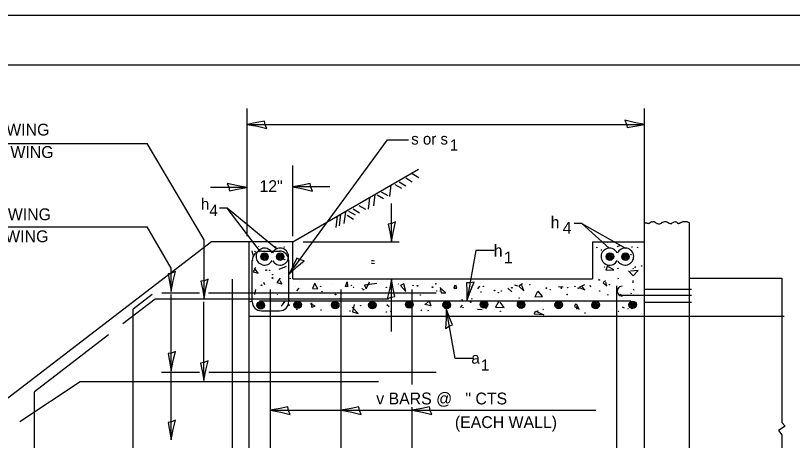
# Model space of a CAD drawing. Extents: x 2133490 to 2172050, y 2138301 to 2145980.
# Drawn here: x 2143369.1 to 2143762.6, y 2145459.3 to 2145674.5 of the extents above; entities that cross this region are included whole.
import ezdxf

# ---------------------------------------------------------------- set-up
doc = ezdxf.new("R2010")
doc.units = 0
for name, color, linetype in [('Level 40', 7, 'Continuous'), ('Level 63', 7, 'Continuous'), ('ROW_PR_Notes', 7, 'Continuous'), ('Sheets_50 Reference Boundary', 7, 'Continuous'), ('Sheets_General Details', 7, 'Continuous'), ('Sheets_Printer Plotting Border', 7, 'Continuous')]:
    doc.layers.add(name, color=color, linetype=linetype)

msp = doc.modelspace()

# ---------------------------------------------------------------- linework, layer by layer
at = {"layer": 'Level 40'}
for p, q in [((2143656, 2145569.17), (2143651.99, 2145569.17)), ((2143669.72, 2145556.75), (2143656, 2145569.17)), ((2143656, 2145569.17), (2143677.98, 2145556.74)), ((2143687.75, 2145535.94), (2143711.4, 2145535.94)), ((2143711.4, 2145532.64), (2143687.75, 2145532.64)), ((2143687.75, 2145529.34), (2143711.4, 2145529.34)), ((2143687.74, 2145522.23), (2143734.89, 2145522.23)), ((2143734.89, 2145522.23), (2143758.47, 2145522.23))]:
    msp.add_line(p, q, dxfattribs=at)
for centre, radius in [((2143505.18, 2145557.27), 0.0943), ((2143663.47, 2145557.02), 0.0943), ((2143668.62, 2145559.72), 0.0943), ((2143681.38, 2145557.27), 0.0943), ((2143684.08, 2145557.02), 0.0943), ((2143490.46, 2145555.06), 0.0943), ((2143495.22, 2145552.4), 1.89), ((2143494.2, 2145552.74), 0.472), ((2143495.22, 2145552.4), 1.41), ((2143495.22, 2145552.4), 0.943), ((2143494.88, 2145552.74), 0.472), ((2143495.22, 2145552.4), 0.472), ((2143496.24, 2145552.06), 0.472), ((2143503.13, 2145552.4), 1.89), ((2143502.11, 2145552.74), 0.472), ((2143503.13, 2145552.4), 1.41), ((2143503.13, 2145552.4), 0.943), ((2143502.79, 2145552.74), 0.472), ((2143503.13, 2145552.4), 0.472), ((2143504.16, 2145552.06), 0.472), ((2143670.17, 2145552.4), 1.89), ((2143669.14, 2145552.74), 0.472), ((2143670.17, 2145552.4), 1.41), ((2143670.17, 2145552.4), 0.943), ((2143669.82, 2145552.74), 0.472), ((2143670.17, 2145552.4), 0.472), ((2143671.19, 2145552.06), 0.472), ((2143678.08, 2145552.4), 1.89), ((2143677.06, 2145552.74), 0.472), ((2143676.72, 2145552.61), 0.0943), ((2143678.08, 2145552.4), 1.41), ((2143678.08, 2145552.4), 0.943), ((2143677.74, 2145552.74), 0.472), ((2143678.08, 2145552.4), 0.472), ((2143679.1, 2145552.06), 0.472), ((2143680.89, 2145553.34), 0.0943), ((2143488.99, 2145550.4), 0.0943), ((2143496.35, 2145550.64), 0.0943), ((2143505.43, 2145550.89), 0.0943), ((2143496.1, 2145545.49), 0.189), ((2143497.82, 2145545.49), 0.0943), ((2143667.39, 2145547.21), 0.0943), ((2143674.26, 2145546.47), 0.0943), ((2143681.87, 2145546.22), 0.0943), ((2143686.29, 2145547.7), 0.0943), ((2143499.29, 2145541.56), 0.189), ((2143499.29, 2145543.28), 0.0943), ((2143508.13, 2145541.32), 0.0943), ((2143664.69, 2145540.58), 0.189), ((2143674.26, 2145541.32), 0.0943), ((2143493.65, 2145537.88), 0.189), ((2143523.59, 2145537.39), 0.0943), ((2143539.29, 2145537.88), 0.0943), ((2143540.28, 2145536.9), 0.0943), ((2143556.96, 2145536.9), 0.0943), ((2143570.46, 2145537.88), 0.0943), ((2143572.67, 2145537.64), 0.189), ((2143580.28, 2145536.9), 0.189), ((2143581.99, 2145538.62), 0.0943), ((2143600.15, 2145536.9), 0.189), ((2143606.04, 2145537.39), 0.0943), ((2143620.52, 2145536.65), 0.189), ((2143629.6, 2145538.13), 0.0943), ((2143648.74, 2145536.65), 0.0943), ((2143652.42, 2145537.39), 0.0943), ((2143669.85, 2145538.13), 0.0943), ((2143524.32, 2145534.69), 0.0943), ((2143531.2, 2145533.22), 0.189), ((2143544.69, 2145536.16), 0.0943), ((2143545.43, 2145535.67), 0.189), ((2143574.14, 2145532.97), 0.0943), ((2143582.48, 2145534.94), 0.0943), ((2143604.82, 2145534.45), 0.0943), ((2143611.69, 2145535.18), 0.189), ((2143613.65, 2145534.2), 0.0943), ((2143615.12, 2145534.94), 0.0943), ((2143637.94, 2145536.41), 0.189), ((2143639.91, 2145535.67), 0.0943), ((2143645.55, 2145536.41), 0.189), ((2143648.5, 2145533.22), 0.0943), ((2143654.14, 2145536.41), 0.189), ((2143664.94, 2145534.94), 0.0943), ((2143675.49, 2145533.22), 0.0943), ((2143680.89, 2145533.71), 0.0943), ((2143488.25, 2145529.54), 0.0943), ((2143493.29, 2145527.76), 1.89), ((2143493.29, 2145527.76), 1.41), ((2143507.88, 2145530.03), 0.0943), ((2143512, 2145528.01), 1.89), ((2143512, 2145528.01), 1.41), ((2143512, 2145528.01), 0.943), ((2143531.04, 2145527.84), 1.89), ((2143531.04, 2145527.84), 1.41), ((2143549.83, 2145527.84), 1.89), ((2143549.83, 2145527.84), 1.41), ((2143548.62, 2145529.78), 0.0943), ((2143568.54, 2145528.17), 1.89), ((2143567.52, 2145528.51), 0.472), ((2143568.54, 2145528.17), 1.41), ((2143568.54, 2145528.17), 0.943), ((2143568.2, 2145528.51), 0.472), ((2143587.5, 2145527.92), 1.89), ((2143587.5, 2145527.92), 1.41), ((2143595.25, 2145530.52), 0.0943), ((2143599.66, 2145529.29), 0.189), ((2143600.15, 2145531.01), 0.0943), ((2143606.37, 2145528.17), 1.89), ((2143605.35, 2145528.51), 0.472), ((2143606.37, 2145528.17), 1.41), ((2143606.37, 2145528.17), 0.943), ((2143606.03, 2145528.51), 0.472), ((2143625.16, 2145528.09), 1.89), ((2143624.14, 2145528.43), 0.472), ((2143625.16, 2145528.09), 1.41), ((2143624.2, 2145531.5), 0.0943), ((2143625.16, 2145528.09), 0.943), ((2143624.82, 2145528.43), 0.472), ((2143644.2, 2145527.92), 1.89), ((2143644.2, 2145527.92), 1.41), ((2143662.91, 2145527.92), 1.89), ((2143662.91, 2145527.92), 1.41), ((2143681.7, 2145528.01), 1.89), ((2143681.7, 2145528.01), 1.41), ((2143681.7, 2145528.01), 0.943), ((2143492.26, 2145528.1), 0.472), ((2143493.29, 2145527.76), 0.943), ((2143492.95, 2145528.1), 0.472), ((2143493.29, 2145527.76), 0.472), ((2143494.31, 2145527.42), 0.472), ((2143495.12, 2145524.88), 0.0943), ((2143507.64, 2145527.82), 0.189), ((2143510.97, 2145528.35), 0.472), ((2143511.66, 2145528.35), 0.472), ((2143511.56, 2145525.61), 0.0943), ((2143512, 2145528.01), 0.472), ((2143513.02, 2145527.67), 0.472), ((2143523.83, 2145525.37), 0.0943), ((2143530.01, 2145528.18), 0.472), ((2143531.04, 2145527.84), 0.943), ((2143530.7, 2145528.18), 0.472), ((2143531.04, 2145527.84), 0.472), ((2143532.06, 2145527.5), 0.472), ((2143538.56, 2145524.88), 0.0943), ((2143543.96, 2145527.58), 0.0943), ((2143548.81, 2145528.18), 0.472), ((2143549.83, 2145527.84), 0.943), ((2143549.49, 2145528.18), 0.472), ((2143549.83, 2145527.84), 0.472), ((2143550.85, 2145527.5), 0.472), ((2143568.54, 2145528.17), 0.472), ((2143569.56, 2145527.83), 0.472), ((2143578.07, 2145525.12), 0.0943), ((2143586.47, 2145528.26), 0.472), ((2143587.5, 2145527.92), 0.943), ((2143587.15, 2145528.26), 0.472), ((2143587.5, 2145527.92), 0.472), ((2143587.88, 2145528.31), 0.189), ((2143588.52, 2145527.58), 0.472), ((2143595.74, 2145526.59), 0.0943), ((2143606.37, 2145528.17), 0.472), ((2143607.39, 2145527.83), 0.472), ((2143607.27, 2145526.35), 0.189), ((2143625.16, 2145528.09), 0.472), ((2143626.18, 2145527.75), 0.472), ((2143633.53, 2145524.88), 0.0943), ((2143643.18, 2145528.26), 0.472), ((2143644.2, 2145527.92), 0.943), ((2143643.86, 2145528.26), 0.472), ((2143644.2, 2145527.92), 0.472), ((2143645.22, 2145527.58), 0.472), ((2143661.89, 2145528.26), 0.472), ((2143662.91, 2145527.92), 0.943), ((2143662.57, 2145528.26), 0.472), ((2143662.91, 2145527.92), 0.472), ((2143663.93, 2145527.58), 0.472), ((2143680.68, 2145528.35), 0.472), ((2143681.36, 2145528.35), 0.472), ((2143681.7, 2145528.01), 0.472), ((2143681.38, 2145526.1), 0.0943), ((2143682.73, 2145527.67), 0.472), ((2143556.96, 2145524.39), 0.0943), ((2143614.63, 2145524.63), 0.0943), ((2143657.58, 2145523.89), 0.0943), ((2143674.51, 2145524.63), 0.0943)]:
    msp.add_circle(centre, radius, dxfattribs=at)
for centre, start, end in [((2143495.22, 2145552.4), 24.9941, 332.0982), ((2143503.13, 2145552.4), 209.5562, 156.8179), ((2143669.99, 2145552.39), 24.9941, 332.0982), ((2143677.91, 2145552.39), 209.5562, 156.8179)]:
    msp.add_arc(centre, 4.3, start, end, dxfattribs=at)
msp.add_spline([(2143687.73, 2145569.53), (2143688.74, 2145569.46), (2143689.34, 2145569.25), (2143690.07, 2145569.25), (2143690.42, 2145569.42), (2143691.02, 2145569.93), (2143691.36, 2145570.11), (2143691.79, 2145570.02), (2143692.61, 2145570.19), (2143693.43, 2145569.46), (2143693.98, 2145569.16), (2143694.71, 2145569.03), (2143695.23, 2145568.99), (2143695.7, 2145569.16), (2143696.39, 2145569.55), (2143696.69, 2145569.76), (2143696.95, 2145569.81), (2143697.89, 2145570.24), (2143698.54, 2145570.15), (2143699.05, 2145569.98), (2143699.74, 2145569.59), (2143700.64, 2145569.12), (2143700.9, 2145569.08), (2143701.33, 2145569.12), (2143701.76, 2145569.42), (2143702.49, 2145569.89), (2143703.01, 2145570.11), (2143703.65, 2145569.98), (2143704.3, 2145569.55), (2143704.43, 2145569.38), (2143704.68, 2145569.2), (2143705.24, 2145569.29), (2143705.76, 2145569.51), (2143706.74, 2145570.02), (2143707.52, 2145570.24), (2143708.29, 2145570.19), (2143709.06, 2145570.11), (2143709.75, 2145569.81), (2143710.4, 2145569.42)], degree=3, dxfattribs=at)
at = {"layer": 'Level 63'}
for p, q in [((2143507.65, 2145543.5), (2143557.52, 2145611.46)), ((2143557.52, 2145611.46), (2143568.06, 2145611.46)), ((2143509.5, 2145562.78), (2143509.5, 2145598.58)), ((2143486.31, 2145587.4), (2143467.89, 2145587.4)), ((2143528.25, 2145587.7), (2143509.5, 2145587.7))]:
    msp.add_line(p, q, dxfattribs=at)
for points in [[(2143496.35, 2145617.27), (2143495.54, 2145619.19), (2143495.22, 2145621.03), (2143491.35, 2145620.23), (2143486.35, 2145619.36), (2143491.69, 2145618.39)], [(2143677.75, 2145621.45), (2143678.56, 2145619.53), (2143678.87, 2145617.69), (2143682.74, 2145618.49), (2143687.74, 2145619.36), (2143682.41, 2145620.33)], [(2143476.31, 2145589.49), (2143477.12, 2145587.57), (2143477.44, 2145585.73), (2143481.31, 2145586.53), (2143486.31, 2145587.4), (2143480.97, 2145588.37)], [(2143519.5, 2145585.61), (2143518.68, 2145587.53), (2143518.37, 2145589.37), (2143514.5, 2145588.56), (2143509.5, 2145587.7), (2143514.83, 2145586.73)], [(2143561.61, 2145569.95), (2143559.69, 2145569.14), (2143557.84, 2145568.82), (2143558.65, 2145564.95), (2143559.52, 2145559.95), (2143560.49, 2145565.29)], [(2143515.25, 2145550.32), (2143513.22, 2145550.8), (2143511.55, 2145551.64), (2143509.91, 2145548.04), (2143507.65, 2145543.5), (2143511.59, 2145547.23)], [(2143450.11, 2145544.79), (2143448.18, 2145543.97), (2143446.34, 2145543.66), (2143447.15, 2145539.79), (2143448.01, 2145534.79), (2143448.98, 2145540.12)], [(2143466.7, 2145541.02), (2143464.77, 2145540.21), (2143462.93, 2145539.89), (2143463.74, 2145536.02), (2143464.6, 2145531.02), (2143465.57, 2145536.36)], [(2143557.42, 2145531.05), (2143559.35, 2145531.87), (2143561.19, 2145532.18), (2143560.38, 2145536.05), (2143559.52, 2145541.05), (2143558.55, 2145535.72)], [(2143601.45, 2145539.53), (2143599.42, 2145539.07), (2143597.55, 2145539.09), (2143597.66, 2145535.13), (2143597.63, 2145530.06), (2143599.53, 2145535.14)], [(2143586.96, 2145516.03), (2143588.71, 2145517.17), (2143590.47, 2145517.8), (2143588.99, 2145521.47), (2143587.26, 2145526.24), (2143587.24, 2145520.82)], [(2143450.11, 2145504.4), (2143448.18, 2145503.58), (2143446.34, 2145503.27), (2143447.15, 2145499.4), (2143448.01, 2145494.4), (2143448.98, 2145499.73)], [(2143466.62, 2145499.59), (2143464.7, 2145498.78), (2143462.86, 2145498.46), (2143463.66, 2145494.59), (2143464.53, 2145489.59), (2143465.5, 2145494.93)], [(2143508.13, 2145472.49), (2143507.31, 2145474.41), (2143507, 2145476.25), (2143503.13, 2145475.45), (2143498.13, 2145474.58), (2143503.46, 2145473.61)], [(2143544.09, 2145472.49), (2143543.28, 2145474.41), (2143542.96, 2145476.25), (2143539.09, 2145475.45), (2143534.09, 2145474.58), (2143539.43, 2145473.61)], [(2143579.93, 2145472.49), (2143579.12, 2145474.41), (2143578.8, 2145476.25), (2143574.93, 2145475.45), (2143569.93, 2145474.58), (2143575.27, 2145473.61)], [(2143450.11, 2145469.56), (2143448.18, 2145468.75), (2143446.34, 2145468.43), (2143447.15, 2145464.56), (2143448.01, 2145459.56), (2143448.98, 2145464.9)]]:
    msp.add_lwpolyline(points, close=True, dxfattribs=at)
at = {"layer": 'ROW_PR_Notes'}
for p, q in [((2143486.35, 2145562.78), (2143486.35, 2145627.41)), ((2143687.74, 2145562.78), (2143687.74, 2145627.41)), ((2143486.35, 2145619.36), (2143687.74, 2145619.36)), ((2143266.28, 2145609.67), (2143435.74, 2145609.67)), ((2143464.6, 2145560.86), (2143435.74, 2145609.67)), ((2143509.5, 2145559.95), (2143573.13, 2145596.69)), ((2143566.78, 2145592.3), (2143570.08, 2145590.34)), ((2143570.08, 2145594.4), (2143573.39, 2145592.45)), ((2143559.27, 2145588.69), (2143558.52, 2145582.84)), ((2143561.22, 2145588.99), (2143564.53, 2145587.04)), ((2143563.48, 2145590.19), (2143566.78, 2145588.24)), ((2143554.32, 2145585.24), (2143557.62, 2145583.29)), ((2143548.46, 2145582.24), (2143547.71, 2145576.38)), ((2143551.16, 2145583.89), (2143550.41, 2145578.03)), ((2143552.22, 2145583.74), (2143555.52, 2145581.79)), ((2143476.38, 2145576.98), (2143472.37, 2145576.98)), ((2143501.28, 2145556.3), (2143476.38, 2145576.98)), ((2143493.17, 2145554.8), (2143476.38, 2145576.98)), ((2143540.05, 2145576.53), (2143543.36, 2145574.58)), ((2143543.06, 2145578.33), (2143546.36, 2145576.38)), ((2143559.52, 2145559.95), (2143559.52, 2145579.26)), ((2143532.09, 2145572.93), (2143531.34, 2145567.07)), ((2143533.75, 2145573.83), (2143532.99, 2145567.97)), ((2143536.15, 2145575.03), (2143535.4, 2145569.17)), ((2143537.05, 2145573.38), (2143540.35, 2145571.42)), ((2143537.8, 2145575.48), (2143541.1, 2145573.53)), ((2143687.74, 2145559.99), (2143687.74, 2145569.42)), ((2143710.4, 2145308.17), (2143710.4, 2145569.42)), ((2143266.5, 2145567.48), (2143435.84, 2145567.48)), ((2143448.01, 2145546.5), (2143435.84, 2145567.48)), ((2143464.6, 2145531.02), (2143464.6, 2145560.86)), ((2143468.41, 2145559.95), (2143355.43, 2145473.2)), ((2143509.5, 2145559.95), (2143468.41, 2145559.95)), ((2143509.5, 2145559.95), (2143486.35, 2145559.95)), ((2143487.45, 2145308.17), (2143487.45, 2145559.95)), ((2143492.18, 2145557.51), (2143492.18, 2145557.27)), ((2143501.26, 2145557.02), (2143500.03, 2145557.51)), ((2143509.5, 2145541.09), (2143509.5, 2145559.95)), ((2143514.8, 2145559.95), (2143563.44, 2145559.95)), ((2143661.3, 2145559.95), (2143687.74, 2145559.95)), ((2143661.3, 2145559.95), (2143661.3, 2145541.09)), ((2143673.77, 2145557.51), (2143675.25, 2145558)), ((2143687.74, 2145371.35), (2143687.74, 2145559.99)), ((2143488.73, 2145555.29), (2143489.28, 2145553.13)), ((2143493.7, 2145555.19), (2143502.82, 2145555.19)), ((2143665.67, 2145556.04), (2143665.67, 2145555.55)), ((2143488.98, 2145529.69), (2143488.98, 2145550.47)), ((2143507.54, 2145529.69), (2143507.54, 2145550.47)), ((2143448.01, 2145534.79), (2143448.01, 2145546.5)), ((2143490.7, 2145546.96), (2143489.48, 2145544.75)), ((2143489.48, 2145544.75), (2143491.93, 2145544.02)), ((2143491.93, 2145544.02), (2143490.21, 2145546.47)), ((2143502.61, 2145546.1), (2143506.39, 2145547.54)), ((2143668.87, 2145547.7), (2143668.13, 2145545.49)), ((2143668.13, 2145545.49), (2143672.06, 2145545.73)), ((2143672.06, 2145545.73), (2143669.36, 2145547.21)), ((2143679.55, 2145545.2), (2143681.89, 2145542.68)), ((2143684.41, 2145545.38), (2143680.63, 2145545.02)), ((2143681.89, 2145542.68), (2143684.41, 2145545.38)), ((2143683.1, 2145547.45), (2143682.61, 2145546.72)), ((2143479.06, 2145313.71), (2143479.06, 2145541.01)), ((2143497.57, 2145544.26), (2143497.57, 2145544.26)), ((2143503.22, 2145541.56), (2143501.5, 2145539.35)), ((2143509.5, 2145541.09), (2143661.3, 2145541.09)), ((2143559.52, 2145514.48), (2143559.52, 2145541.05)), ((2143710.14, 2145541.4), (2143757.29, 2145541.4)), ((2143757.29, 2145541.4), (2143757.29, 2145468.37)), ((2143495.4, 2145538.17), (2143494.86, 2145539.25)), ((2143501.5, 2145539.35), (2143503.96, 2145538.62)), ((2143503.96, 2145538.62), (2143503.22, 2145540.09)), ((2143510.9, 2145537.09), (2143510.9, 2145537.09)), ((2143513.04, 2145539.6), (2143513.04, 2145539.6)), ((2143520.63, 2145538.9), (2143519.55, 2145536.19)), ((2143522.25, 2145536.01), (2143520.63, 2145538.72)), ((2143520.64, 2145538.37), (2143521.14, 2145538.62)), ((2143529.72, 2145538.62), (2143529.72, 2145538.62)), ((2143536.3, 2145537.27), (2143537.02, 2145539.62)), ((2143537.56, 2145537.27), (2143536.3, 2145537.27)), ((2143537.02, 2145539.62), (2143537.2, 2145537.27)), ((2143537.09, 2145537.14), (2143537.09, 2145537.14)), ((2143552.06, 2145538.86), (2143545.92, 2145537.88)), ((2143545.92, 2145537.88), (2143546.66, 2145536.16)), ((2143546.66, 2145536.16), (2143548.37, 2145539.6)), ((2143562.85, 2145538.62), (2143563.1, 2145538.37)), ((2143565.85, 2145538.53), (2143564.05, 2145537.81)), ((2143564.05, 2145537.81), (2143566.75, 2145534.75)), ((2143566.75, 2145534.75), (2143565.85, 2145538.53)), ((2143591.56, 2145537.88), (2143591.07, 2145536.41)), ((2143592.54, 2145536.41), (2143592.05, 2145537.88)), ((2143604.08, 2145537.39), (2143603.1, 2145536.16)), ((2143623.46, 2145537.39), (2143621.99, 2145537.88)), ((2143625.85, 2145538.53), (2143624.05, 2145537.45)), ((2143624.05, 2145537.45), (2143626.57, 2145535.11)), ((2143626.57, 2145535.11), (2143625.49, 2145537.81)), ((2143646.53, 2145536.9), (2143644.08, 2145537.14)), ((2143657.2, 2145538.17), (2143654.5, 2145536.73)), ((2143657.38, 2145535.65), (2143656.12, 2145537.09)), ((2143660.03, 2145537.88), (2143660.28, 2145537.14)), ((2143667.88, 2145540.09), (2143666.66, 2145539.11)), ((2143666.66, 2145539.11), (2143668.62, 2145537.39)), ((2143668.62, 2145537.39), (2143668.13, 2145539.35)), ((2143673.61, 2145393.47), (2143673.61, 2145537.55)), ((2143681.87, 2145539.11), (2143681.87, 2145540.33)), ((2143438.25, 2145533.21), (2143428.67, 2145525.86)), ((2143443.21, 2145534.02), (2143462.28, 2145534.02)), ((2143448.01, 2145494.4), (2143448.01, 2145533.29)), ((2143466.78, 2145534.02), (2143582.12, 2145534.02)), ((2143490.7, 2145535.67), (2143490.21, 2145533.22)), ((2143498.27, 2145393.16), (2143498.27, 2145535.74)), ((2143501.75, 2145533.22), (2143501.75, 2145533.46)), ((2143511.62, 2145535.11), (2143512.7, 2145536.37)), ((2143515.74, 2145535.18), (2143515.74, 2145535.18)), ((2143519.55, 2145536.19), (2143522.25, 2145536.01)), ((2143534.1, 2145393.16), (2143534.1, 2145535.74)), ((2143569.93, 2145487.64), (2143569.93, 2145535.74)), ((2143583.96, 2145535.18), (2143584.2, 2145534.94)), ((2143584.23, 2145536.73), (2143584.77, 2145534.03)), ((2143587.11, 2145534.03), (2143584.23, 2145536.55)), ((2143584.77, 2145534.03), (2143587.11, 2145534.03)), ((2143591.07, 2145536.41), (2143592.54, 2145536.41)), ((2143620.45, 2145534.57), (2143618.46, 2145536.37)), ((2143633.53, 2145534.69), (2143632.05, 2145531.99)), ((2143635.98, 2145532.24), (2143633.77, 2145534.94)), ((2143654.5, 2145536.73), (2143657.38, 2145535.65)), ((2143668.87, 2145532.97), (2143669.36, 2145533.22)), ((2143682.36, 2145535.18), (2143682.12, 2145535.92)), ((2143439.75, 2145530.81), (2143423.48, 2145518.31)), ((2143558, 2145530.81), (2143439.75, 2145530.81)), ((2143464.53, 2145489.59), (2143464.53, 2145529.53)), ((2143680.69, 2145529.91), (2143492.72, 2145529.91)), ((2143505.43, 2145529.78), (2143503.71, 2145527.33)), ((2143505.43, 2145529.54), (2143505.43, 2145529.78)), ((2143518.93, 2145529.05), (2143518.93, 2145526.84)), ((2143576.48, 2145527.9), (2143578.65, 2145530.07)), ((2143578.65, 2145530.07), (2143579.37, 2145527.54)), ((2143613.65, 2145529.54), (2143612.18, 2145526.84)), ((2143616.6, 2145526.59), (2143614.63, 2145529.29)), ((2143632.05, 2145531.99), (2143635.98, 2145532.24)), ((2143687.75, 2145532.64), (2143675.73, 2145532.64)), ((2143428.67, 2145406.61), (2143428.67, 2145525.86)), ((2143493.7, 2145524.98), (2143502.82, 2145524.98)), ((2143520.89, 2145527.33), (2143518.44, 2145528.56)), ((2143518.93, 2145526.84), (2143520.89, 2145527.33)), ((2143542.61, 2145523.58), (2143539.55, 2145526.82)), ((2143540.63, 2145528.08), (2143539.73, 2145524.48)), ((2143540.28, 2145526.1), (2143540.52, 2145526.1)), ((2143557.21, 2145528.07), (2143558.43, 2145527.08)), ((2143574.39, 2145524.88), (2143574.88, 2145525.37)), ((2143579.37, 2145527.54), (2143576.48, 2145528.08)), ((2143579.29, 2145526.59), (2143579.29, 2145526.59)), ((2143594.51, 2145526.59), (2143595.49, 2145527.82)), ((2143605.49, 2145525.38), (2143603.15, 2145525.56)), ((2143612.18, 2145526.84), (2143616.6, 2145526.59)), ((2143636.23, 2145525.37), (2143636.47, 2145525.86)), ((2143652.67, 2145528.56), (2143652.18, 2145527.08)), ((2143652.18, 2145527.08), (2143654.63, 2145525.86)), ((2143654.63, 2145525.86), (2143653.16, 2145528.31)), ((2143653.41, 2145525.86), (2143653.41, 2145527.08)), ((2143671.32, 2145525.86), (2143671.32, 2145525.86)), ((2143677.56, 2145526.28), (2143676.48, 2145526.82)), ((2143679.42, 2145525.86), (2143679.42, 2145526.1)), ((2143487.45, 2145522.23), (2143687.74, 2145522.23)), ((2143539.73, 2145524.48), (2143542.61, 2145523.58)), ((2143559.17, 2145524.39), (2143559.42, 2145524.88)), ((2143631.8, 2145523.4), (2143632.7, 2145524.84)), ((2143636.66, 2145522.86), (2143631.8, 2145523.22)), ((2143632.7, 2145524.84), (2143636.66, 2145522.86)), ((2143416.23, 2145512.75), (2143378.75, 2145483.97)), ((2143443.11, 2145493.94), (2143462.28, 2145493.94)), ((2143467.08, 2145493.94), (2143582.12, 2145493.94)), ((2143448.01, 2145459.56), (2143448.01, 2145493.35)), ((2143371.27, 2145468.93), (2143401.89, 2145489.23)), ((2143401.89, 2145489.23), (2143553, 2145489.23)), ((2143378.75, 2145313.71), (2143378.75, 2145483.97)), ((2143498.13, 2145474.58), (2143534.09, 2145474.58)), ((2143534.09, 2145474.58), (2143570.57, 2145474.58)), ((2143569.93, 2145393.16), (2143569.93, 2145476.09)), ((2143569.93, 2145474.58), (2143660.84, 2145474.58)), ((2143660.84, 2145474.58), (2143663.09, 2145474.58)), ((2143759, 2145466.61), (2143755.56, 2145464.38)), ((2143757.29, 2145468.37), (2143759, 2145466.61)), ((2143755.56, 2145464.38), (2143757.29, 2145462.19)), ((2143757.29, 2145462.19), (2143757.29, 2145389.9))]:
    msp.add_line(p, q, dxfattribs=at)
for points in [[(2143611.6, 2145555.43), (2143602.17, 2145555.43), (2143597.63, 2145530.06)], [(2143601.22, 2145500.86), (2143591.79, 2145500.86), (2143587.26, 2145526.24)]]:
    msp.add_lwpolyline(points, dxfattribs=at)
for centre, radius, start, end in [((2143493.7, 2145550.47), 4.72, 90, 180), ((2143502.82, 2145550.47), 4.72, 0, 90), ((2143676.36, 2145534.94), 2.48, 91.2091, 272.0621), ((2143493.7, 2145529.69), 4.72, 180, 270), ((2143502.82, 2145529.69), 4.72, 270, 0)]:
    msp.add_arc(centre, radius, start, end, dxfattribs=at)
at = {"layer": 'Sheets_50 Reference Boundary'}
msp.add_lwpolyline([(2143250.12, 2145649.45), (2144825.12, 2145649.45), (2144825.12, 2144649.46), (2143250.12, 2144649.46)], close=True, dxfattribs=at)
at = {"layer": 'Sheets_General Details'}
msp.add_line((2144850.12, 2145674.46), (2143150.12, 2145674.46), dxfattribs=at)
msp.add_lwpolyline([(2143250.12, 2145649.46), (2144825.12, 2145649.46), (2144825.12, 2144599.46), (2143250.12, 2144599.46)], close=True, dxfattribs=at)
at = {"layer": 'Sheets_Printer Plotting Border'}
msp.add_lwpolyline([(2143150.12, 2144574.46), (2144850.12, 2144574.46), (2144850.12, 2145674.46), (2143150.12, 2145674.46)], close=True, dxfattribs=at)

# ---------------------------------------------------------------- texts
at = {"layer": 'Level 63'}
for s, p in [('  - #  h   @   " CTS SHORT WING', (2143266.49, 2145613.7)), ('  - #  h   @   " CTS LONG WING', (2143273.95, 2145602.34)), ('12"', (2143492.66, 2145585.08)), ('  - #  h   @   " CTS SHORT WING', (2143267.3, 2145570.82)), ('  - #  h   @   " CTS LONG WING', (2143271.33, 2145559.69)), ('      v BARS @   " CTS', (2143538.44, 2145477.55))]:
    msp.add_text(s, height=6, dxfattribs=at).set_placement(p)
at = {"layer": 'ROW_PR_Notes'}
for s, height, p in [('s or s', 5.7, (2143569.5, 2145609.13)), ('1', 5.7, (2143589.08, 2145606.03)), ('h ', 5.7, (2143462.99, 2145576.18)), ('4', 5.7, (2143467.3, 2145572.93)), ('h ', 6, (2143640.17, 2145566.73)), ('4', 6, (2143646.26, 2145563.97)), (' h ', 6, (2143609.08, 2145552.43)), ('1', 6, (2143616.45, 2145548.97)), (' a ', 5.7, (2143597.87, 2145498.18)), ('1', 5.7, (2143604.84, 2145494.66)), ('(EACH WALL)', 6, (2143591.64, 2145465.58))]:
    msp.add_text(s, height=height, dxfattribs=at).set_placement(p)
msp.add_text('  "', height=5.7, rotation=90, dxfattribs=at).set_placement((2143554.99, 2145544.03))

doc.saveas('drawing.dxf')
